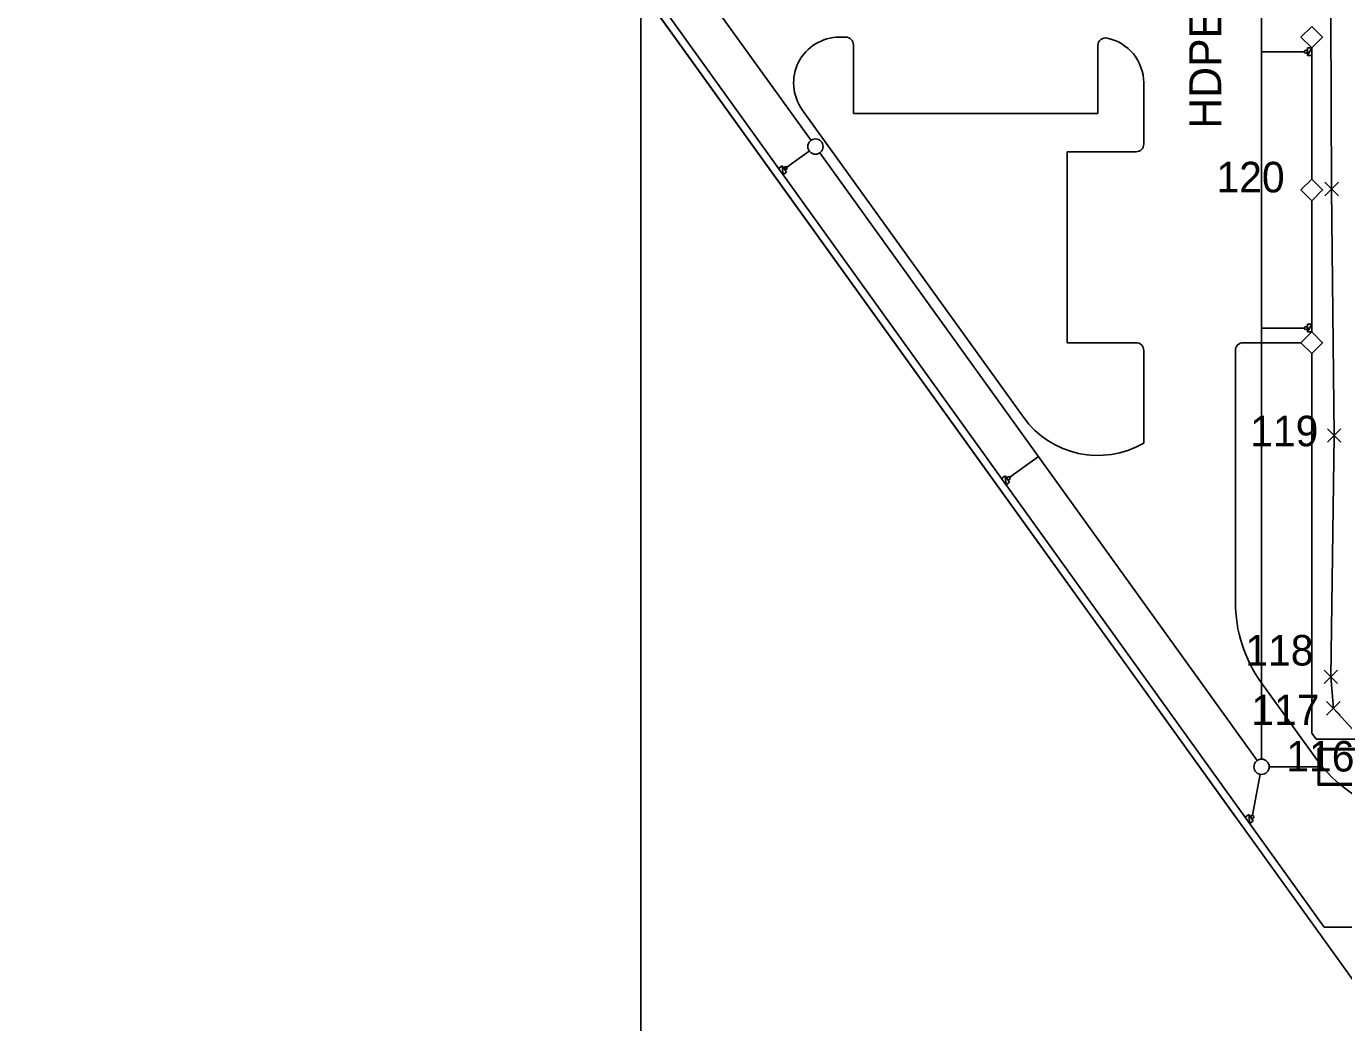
# Model space of a CAD drawing. Extents: x -264205 to -263744, y -1242450 to -1242050.
# Drawn here: x -264204.7 to -264118.5, y -1242315 to -1242249.8 of the extents above; entities that cross this region are included whole.
import ezdxf

# ---------------------------------------------------------------- set-up
doc = ezdxf.new("R2010")
doc.units = 0
for name, color, linetype in [('KFA_63-1_TELEKOM_PRELOZKA', 7, 'Continuous'), ('KFA_BODY_CISLO', 7, 'Continuous'), ('KFA_BODY_SYMBOL', 7, 'Continuous'), ('KFA_SITUACIA_DSP', 7, 'Continuous'), ('POPIS', 7, 'Continuous'), ('RAM_NA_TLAC_A3_1-1000', 7, 'Continuous')]:
    doc.layers.add(name, color=color, linetype=linetype)

msp = doc.modelspace()

# ---------------------------------------------------------------- linework, layer by layer
at = {"layer": 'KFA_63-1_TELEKOM_PRELOZKA'}
msp.add_lwpolyline([(-264117.865, -1242295.81), (-264119.153, -1242294.416), (-264119.323, -1242292.348), (-264119.1, -1242276.55), (-264119.268, -1242260.421), (-264119.343, -1242243.475), (-264119.114, -1242230.399), (-264119.258, -1242210.402), (-264119.476, -1242195.245), (-264119.832, -1242189.966), (-264120.07, -1242187.778), (-264119.914, -1242186.996), (-264119.225, -1242186.724), (-264097.679, -1242186.215)], dxfattribs=at)
at = {"layer": 'KFA_BODY_SYMBOL'}
for p, q in [((-264119.71, -1242260.863), (-264118.826, -1242259.979)), ((-264118.826, -1242260.863), (-264119.71, -1242259.979)), ((-264119.268, -1242260.421), (-264119.268, -1242260.421)), ((-264119.542, -1242276.992), (-264118.658, -1242276.108)), ((-264118.658, -1242276.992), (-264119.542, -1242276.108)), ((-264119.1, -1242276.55), (-264119.1, -1242276.55)), ((-264119.765, -1242292.79), (-264118.881, -1242291.906)), ((-264118.881, -1242292.79), (-264119.765, -1242291.906)), ((-264119.323, -1242292.348), (-264119.323, -1242292.348)), ((-264119.595, -1242294.858), (-264118.711, -1242293.974)), ((-264118.711, -1242294.858), (-264119.595, -1242293.974)), ((-264119.153, -1242294.416), (-264119.153, -1242294.416))]:
    msp.add_line(p, q, dxfattribs=at)
at = {"layer": 'KFA_SITUACIA_DSP'}
for p, q in [((-264204.694, -1242191.482), (-264115.871, -1242314.982)), ((-264204.078, -1242191.482), (-264119.75, -1242308.732)), ((-264181.951, -1242217.458), (-264153.34, -1242257.238)), ((-264123.854, -1242237.976), (-264123.854, -1242297.736)), ((-264151.48, -1242250.482), (-264151.068, -1242250.482)), ((-264150.568, -1242255.482), (-264150.568, -1242250.982)), ((-264134.568, -1242255.482), (-264134.568, -1242251.033)), ((-264120.857, -1242251.689), (-264120.857, -1242251.189)), ((-264120.857, -1242251.189), (-264120.567, -1242251.189)), ((-264120.857, -1242251.689), (-264120.567, -1242251.189)), ((-264120.857, -1242251.689), (-264120.567, -1242251.189)), ((-264120.567, -1242251.189), (-264120.857, -1242251.189)), ((-264120.857, -1242251.189), (-264120.857, -1242251.689)), ((-264120.568, -1242251.191), (-264120.568, -1242259.775)), ((-264120.567, -1242251.189), (-264120.567, -1242251.689)), ((-264121.057, -1242251.439), (-264123.853, -1242251.439)), ((-264120.567, -1242251.689), (-264120.857, -1242251.689)), ((-264131.568, -1242257.482), (-264131.568, -1242253.482)), ((-264153.916, -1242255.234), (-264139.439, -1242275.363)), ((-264150.568, -1242255.482), (-264134.568, -1242255.482)), ((-264155.084, -1242259.108), (-264153.454, -1242257.936)), ((-264154.921, -1242258.991), (-264153.454, -1242257.936)), ((-264152.757, -1242258.05), (-264124.146, -1242297.83)), ((-264152.757, -1242258.05), (-264124.146, -1242297.83)), ((-264136.568, -1242257.982), (-264136.568, -1242270.482)), ((-264136.568, -1242257.982), (-264132.068, -1242257.982)), ((-264155.465, -1242259.074), (-264155.23, -1242258.905)), ((-264155.23, -1242258.905), (-264154.938, -1242259.311)), ((-264155.23, -1242258.905), (-264155.173, -1242259.48)), ((-264155.23, -1242258.905), (-264155.173, -1242259.48)), ((-264154.938, -1242259.311), (-264155.23, -1242258.905)), ((-264155.173, -1242259.48), (-264155.465, -1242259.074)), ((-264154.938, -1242259.311), (-264155.173, -1242259.48)), ((-264155.173, -1242259.48), (-264154.938, -1242259.311)), ((-264120.568, -1242261.189), (-264120.568, -1242269.774)), ((-264120.857, -1242269.775), (-264120.857, -1242269.275)), ((-264120.857, -1242269.275), (-264120.567, -1242269.275)), ((-264120.857, -1242269.775), (-264120.567, -1242269.275)), ((-264120.857, -1242269.775), (-264120.567, -1242269.275)), ((-264120.567, -1242269.275), (-264120.857, -1242269.275)), ((-264120.857, -1242269.275), (-264120.857, -1242269.775)), ((-264120.567, -1242269.275), (-264120.567, -1242269.775)), ((-264121.058, -1242269.525), (-264123.854, -1242269.525)), ((-264120.567, -1242269.775), (-264120.857, -1242269.775)), ((-264136.568, -1242270.482), (-264132.068, -1242270.482)), ((-264131.568, -1242270.982), (-264131.568, -1242277.056)), ((-264125.568, -1242287.467), (-264125.568, -1242270.982)), ((-264125.068, -1242270.482), (-264121.275, -1242270.482)), ((-264140.324, -1242279.287), (-264138.451, -1242277.94)), ((-264140.868, -1242279.37), (-264140.632, -1242279.201)), ((-264140.576, -1242279.776), (-264140.868, -1242279.37)), ((-264140.632, -1242279.201), (-264140.341, -1242279.607)), ((-264140.632, -1242279.201), (-264140.576, -1242279.776)), ((-264140.632, -1242279.201), (-264140.576, -1242279.776)), ((-264140.341, -1242279.607), (-264140.632, -1242279.201)), ((-264140.341, -1242279.607), (-264140.576, -1242279.776)), ((-264140.576, -1242279.776), (-264140.341, -1242279.607)), ((-264123.874, -1242292.722), (-264120.268, -1242297.737)), ((-264120.568, -1242296.035), (-264120.282, -1242296.432)), ((-264120.154, -1242297.036), (-264120.154, -1242299.436)), ((-264115.254, -1242297.036), (-264120.154, -1242297.036)), ((-264115.354, -1242297.136), (-264120.054, -1242297.136)), ((-264120.054, -1242297.136), (-264120.054, -1242299.336)), ((-264123.354, -1242298.236), (-264120.154, -1242298.236)), ((-264124.444, -1242301.414), (-264123.946, -1242298.728)), ((-264120.154, -1242299.436), (-264115.254, -1242299.436)), ((-264120.054, -1242299.336), (-264115.354, -1242299.336)), ((-264124.925, -1242301.537), (-264124.69, -1242301.368)), ((-264124.633, -1242301.943), (-264124.925, -1242301.537)), ((-264124.69, -1242301.368), (-264124.398, -1242301.774)), ((-264124.69, -1242301.368), (-264124.633, -1242301.943)), ((-264124.69, -1242301.368), (-264124.633, -1242301.943)), ((-264124.398, -1242301.774), (-264124.69, -1242301.368)), ((-264124.398, -1242301.774), (-264124.633, -1242301.943)), ((-264124.633, -1242301.943), (-264124.398, -1242301.774)), ((-264050.531, -1242308.732), (-264119.75, -1242308.732))]:
    msp.add_line(p, q, dxfattribs=at)
for points in [[(-264204.694, -1242191.482), (-264137.78, -1242284.52), (-264125.581, -1242301.482)], [(-264120.568, -1242296.035), (-264120.568, -1242271.189), (-264120.568, -1242271.189)], [(-263965.143, -1242296.432), (-264120.018, -1242296.432), (-264120.282, -1242296.432)]]:
    msp.add_lwpolyline(points, dxfattribs=at)
for points in [[(-264120.568, -1242249.775), (-264119.861, -1242250.482), (-264120.568, -1242251.189), (-264121.275, -1242250.482)], [(-264120.568, -1242259.775), (-264119.861, -1242260.482), (-264120.568, -1242261.189), (-264121.275, -1242260.482)], [(-264120.568, -1242269.775), (-264119.861, -1242270.482), (-264120.568, -1242271.189), (-264121.275, -1242270.482)]]:
    msp.add_lwpolyline(points, close=True, dxfattribs=at)
for centre, radius in [((-264120.957, -1242251.439), 0.1), ((-264153.049, -1242257.644), 0.5), ((-264155, -1242259.053), 0.1), ((-264120.958, -1242269.525), 0.1), ((-264140.403, -1242279.349), 0.1), ((-264123.854, -1242298.236), 0.5), ((-264124.462, -1242301.513), 0.1)]:
    msp.add_circle(centre, radius, dxfattribs=at)
for centre, radius, start, end in [((-264151.48, -1242253.482), 3, 90, 215.72401), ((-264151.068, -1242250.982), 0.5, 0, 90), ((-264134.068, -1242251.033), 0.5, 78.46304, 180), ((-264134.568, -1242253.482), 3, 0, 78.46304), ((-264132.068, -1242257.482), 0.5, 270, 0), ((-264132.068, -1242270.982), 0.5, 0, 90), ((-264125.068, -1242270.982), 0.5, 90, 180), ((-264134.568, -1242271.86), 6, 215.72401, 300), ((-264116.568, -1242287.467), 9, 180, 215.72401), ((-264112.961, -1242292.482), 9, 215.72401, 270)]:
    msp.add_arc(centre, radius, start, end, dxfattribs=at)
at = {"layer": 'RAM_NA_TLAC_A3_1-1000'}
msp.add_lwpolyline([(-264164.47, -1242072.566), (-263744.47, -1242072.566), (-263744.47, -1242369.566), (-264164.47, -1242369.566)], close=True, dxfattribs=at)

# ---------------------------------------------------------------- texts
at = {"layer": 'KFA_BODY_CISLO'}
for s, p in [('120', (-264126.808, -1242260.642)), ('119', (-264124.598, -1242277.261)), ('118', (-264124.918, -1242291.611)), ('117', (-264124.523, -1242295.512)), ('116', (-264122.238, -1242298.547))]:
    msp.add_text(s, height=2, dxfattribs=at).set_placement(p)
at = {"layer": 'POPIS'}
msp.add_text('HDPE40/34+5x10/8mm', height=2.09, rotation=90, dxfattribs=at).set_placement((-264126.497, -1242256.471))

doc.saveas('drawing.dxf')
